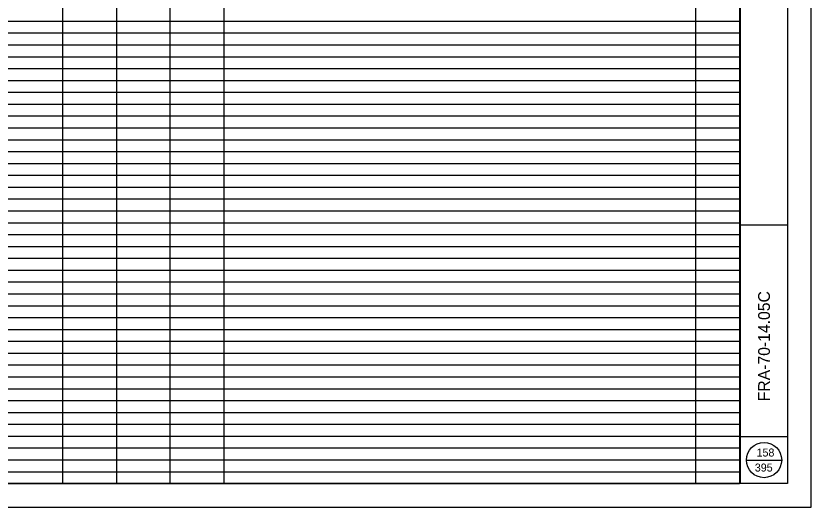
# Model space of a CAD drawing. Extents: x 1826847 to 2221677, y 500657 to 714743.
# Drawn here: x 1827702 to 1828547, y 713643 to 714165 of the extents above; entities that cross this region are included whole.
import ezdxf

# ---------------------------------------------------------------- set-up
doc = ezdxf.new("R2010")
doc.units = 0
for name, color, linetype in [('SH_Border', 7, 'Continuous'), ('SH_Cut_Line', 7, 'Continuous'), ('SH_Data', 7, 'Continuous')]:
    doc.layers.add(name, color=color, linetype=linetype)

msp = doc.modelspace()

# ---------------------------------------------------------------- linework, layer by layer
at = {"layer": 'SH_Border'}
for p, q in [((1828471.62, 713668.08), (1828471.62, 714718.08)), ((1828471.62, 713943.08), (1828521.62, 713943.08)), ((1828471.62, 713718.08), (1828521.62, 713718.08))]:
    msp.add_line(p, q, dxfattribs=at)
msp.add_lwpolyline([(1826946.62, 714718.08), (1828521.62, 714718.08), (1828521.62, 713668.08), (1826946.62, 713668.08)], close=True, dxfattribs=at)
at = {"layer": 'SH_Cut_Line'}
msp.add_lwpolyline([(1826846.62, 713643.08), (1828546.62, 713643.08), (1828546.62, 714743.08), (1826846.62, 714743.08)], close=True, dxfattribs=at)
at = {"layer": 'SH_Data'}
for p, q in [((1827751.22, 714222.48), (1827751.22, 714159.48)), ((1827808.82, 714222.48), (1827808.82, 714159.48)), ((1827865.22, 714222.48), (1827865.22, 714159.48)), ((1827922.82, 714222.48), (1827922.82, 714159.48)), ((1828423.82, 714222.48), (1828423.82, 714159.48)), ((1828470.62, 714222.48), (1828470.62, 714159.48)), ((1827648.62, 714159.48), (1827808.82, 714159.48)), ((1827751.22, 714159.48), (1827751.22, 714096.48)), ((1827808.82, 714159.48), (1827865.22, 714159.48)), ((1827808.82, 714159.48), (1827808.82, 714096.48)), ((1827865.22, 714159.48), (1827922.82, 714159.48)), ((1827865.22, 714159.48), (1827865.22, 714096.48)), ((1827922.82, 714159.48), (1828470.62, 714159.48)), ((1827922.82, 714159.48), (1827922.82, 714096.48)), ((1828423.82, 714159.48), (1828423.82, 714096.48)), ((1828470.62, 714159.48), (1828470.62, 714096.48)), ((1827648.62, 714146.88), (1827808.82, 714146.88)), ((1827808.82, 714146.88), (1827865.22, 714146.88)), ((1827865.22, 714146.88), (1827922.82, 714146.88)), ((1827922.82, 714146.88), (1828470.62, 714146.88)), ((1827648.62, 714134.28), (1827808.82, 714134.28)), ((1827808.82, 714134.28), (1827865.22, 714134.28)), ((1827865.22, 714134.28), (1827922.82, 714134.28)), ((1827922.82, 714134.28), (1828470.62, 714134.28)), ((1827648.62, 714121.68), (1827808.82, 714121.68)), ((1827808.82, 714121.68), (1827865.22, 714121.68)), ((1827865.22, 714121.68), (1827922.82, 714121.68)), ((1827922.82, 714121.68), (1828470.62, 714121.68)), ((1827648.62, 714109.08), (1827808.82, 714109.08)), ((1827808.82, 714109.08), (1827865.22, 714109.08)), ((1827865.22, 714109.08), (1827922.82, 714109.08)), ((1827922.82, 714109.08), (1828470.62, 714109.08)), ((1827648.62, 714096.48), (1827808.82, 714096.48)), ((1827751.22, 714096.48), (1827751.22, 714033.48)), ((1827808.82, 714096.48), (1827865.22, 714096.48)), ((1827808.82, 714096.48), (1827808.82, 714033.48)), ((1827865.22, 714096.48), (1827922.82, 714096.48)), ((1827865.22, 714096.48), (1827865.22, 714033.48)), ((1827922.82, 714096.48), (1828470.62, 714096.48)), ((1827922.82, 714096.48), (1827922.82, 714033.48)), ((1828423.82, 714096.48), (1828423.82, 714033.48)), ((1828470.62, 714096.48), (1828470.62, 714033.48)), ((1827648.62, 714083.88), (1827808.82, 714083.88)), ((1827808.82, 714083.88), (1827865.22, 714083.88)), ((1827865.22, 714083.88), (1827922.82, 714083.88)), ((1827922.82, 714083.88), (1828470.62, 714083.88)), ((1827648.62, 714071.28), (1827808.82, 714071.28)), ((1827808.82, 714071.28), (1827865.22, 714071.28)), ((1827865.22, 714071.28), (1827922.82, 714071.28)), ((1827922.82, 714071.28), (1828470.62, 714071.28)), ((1827648.62, 714058.68), (1827808.82, 714058.68)), ((1827808.82, 714058.68), (1827865.22, 714058.68)), ((1827865.22, 714058.68), (1827922.82, 714058.68)), ((1827922.82, 714058.68), (1828470.62, 714058.68)), ((1827648.62, 714046.08), (1827808.82, 714046.08)), ((1827808.82, 714046.08), (1827865.22, 714046.08)), ((1827865.22, 714046.08), (1827922.82, 714046.08)), ((1827922.82, 714046.08), (1828470.62, 714046.08)), ((1827648.62, 714033.48), (1827808.82, 714033.48)), ((1827751.22, 714033.48), (1827751.22, 713970.48)), ((1827808.82, 714033.48), (1827865.22, 714033.48)), ((1827808.82, 714033.48), (1827808.82, 713970.48)), ((1827865.22, 714033.48), (1827922.82, 714033.48)), ((1827865.22, 714033.48), (1827865.22, 713970.48)), ((1827922.82, 714033.48), (1828470.62, 714033.48)), ((1827922.82, 714033.48), (1827922.82, 713970.48)), ((1828423.82, 714033.48), (1828423.82, 713970.48)), ((1828470.62, 714033.48), (1828470.62, 713970.48)), ((1827648.62, 714020.88), (1827808.82, 714020.88)), ((1827808.82, 714020.88), (1827865.22, 714020.88)), ((1827865.22, 714020.88), (1827922.82, 714020.88)), ((1827922.82, 714020.88), (1828470.62, 714020.88)), ((1827648.62, 714008.28), (1827808.82, 714008.28)), ((1827808.82, 714008.28), (1827865.22, 714008.28)), ((1827865.22, 714008.28), (1827922.82, 714008.28)), ((1827922.82, 714008.28), (1828470.62, 714008.28)), ((1827648.62, 713995.68), (1827808.82, 713995.68)), ((1827808.82, 713995.68), (1827865.22, 713995.68)), ((1827865.22, 713995.68), (1827922.82, 713995.68)), ((1827922.82, 713995.68), (1828470.62, 713995.68)), ((1827648.62, 713983.08), (1827808.82, 713983.08)), ((1827808.82, 713983.08), (1827865.22, 713983.08)), ((1827865.22, 713983.08), (1827922.82, 713983.08)), ((1827922.82, 713983.08), (1828470.62, 713983.08)), ((1827648.62, 713970.48), (1827808.82, 713970.48)), ((1827751.22, 713970.48), (1827751.22, 713907.48)), ((1827808.82, 713970.48), (1827865.22, 713970.48)), ((1827808.82, 713970.48), (1827808.82, 713907.48)), ((1827865.22, 713970.48), (1827922.82, 713970.48)), ((1827865.22, 713970.48), (1827865.22, 713907.48)), ((1827922.82, 713970.48), (1828470.62, 713970.48)), ((1827922.82, 713970.48), (1827922.82, 713907.48)), ((1828423.82, 713970.48), (1828423.82, 713907.48)), ((1828470.62, 713970.48), (1828470.62, 713907.48)), ((1827648.62, 713957.88), (1827808.82, 713957.88)), ((1827808.82, 713957.88), (1827865.22, 713957.88)), ((1827865.22, 713957.88), (1827922.82, 713957.88)), ((1827922.82, 713957.88), (1828470.62, 713957.88)), ((1827648.62, 713945.28), (1827808.82, 713945.28)), ((1827808.82, 713945.28), (1827865.22, 713945.28)), ((1827865.22, 713945.28), (1827922.82, 713945.28)), ((1827922.82, 713945.28), (1828470.62, 713945.28)), ((1827648.62, 713932.68), (1827808.82, 713932.68)), ((1827808.82, 713932.68), (1827865.22, 713932.68)), ((1827865.22, 713932.68), (1827922.82, 713932.68)), ((1827922.82, 713932.68), (1828470.62, 713932.68)), ((1827648.62, 713920.08), (1827808.82, 713920.08)), ((1827808.82, 713920.08), (1827865.22, 713920.08)), ((1827865.22, 713920.08), (1827922.82, 713920.08)), ((1827922.82, 713920.08), (1828470.62, 713920.08)), ((1827648.62, 713907.48), (1827808.82, 713907.48)), ((1827751.22, 713907.48), (1827751.22, 713844.48)), ((1827808.82, 713907.48), (1827865.22, 713907.48)), ((1827808.82, 713907.48), (1827808.82, 713844.48)), ((1827865.22, 713907.48), (1827922.82, 713907.48)), ((1827865.22, 713907.48), (1827865.22, 713844.48)), ((1827922.82, 713907.48), (1828470.62, 713907.48)), ((1827922.82, 713907.48), (1827922.82, 713844.48)), ((1828423.82, 713907.48), (1828423.82, 713844.48)), ((1828470.62, 713907.48), (1828470.62, 713844.48)), ((1827648.62, 713894.88), (1827808.82, 713894.88)), ((1827808.82, 713894.88), (1827865.22, 713894.88)), ((1827865.22, 713894.88), (1827922.82, 713894.88)), ((1827922.82, 713894.88), (1828470.62, 713894.88)), ((1827648.62, 713882.28), (1827808.82, 713882.28)), ((1827808.82, 713882.28), (1827865.22, 713882.28)), ((1827865.22, 713882.28), (1827922.82, 713882.28)), ((1827922.82, 713882.28), (1828470.62, 713882.28)), ((1827648.62, 713869.68), (1827808.82, 713869.68)), ((1827808.82, 713869.68), (1827865.22, 713869.68)), ((1827865.22, 713869.68), (1827922.82, 713869.68)), ((1827922.82, 713869.68), (1828470.62, 713869.68)), ((1827648.62, 713857.08), (1827808.82, 713857.08)), ((1827808.82, 713857.08), (1827865.22, 713857.08)), ((1827865.22, 713857.08), (1827922.82, 713857.08)), ((1827922.82, 713857.08), (1828470.62, 713857.08)), ((1827648.62, 713844.48), (1827808.82, 713844.48)), ((1827751.22, 713844.48), (1827751.22, 713781.48)), ((1827808.82, 713844.48), (1827865.22, 713844.48)), ((1827808.82, 713844.48), (1827808.82, 713781.48)), ((1827865.22, 713844.48), (1827922.82, 713844.48)), ((1827865.22, 713844.48), (1827865.22, 713781.48)), ((1827922.82, 713844.48), (1828470.62, 713844.48)), ((1827922.82, 713844.48), (1827922.82, 713781.48)), ((1828423.82, 713844.48), (1828423.82, 713781.48)), ((1828470.62, 713844.48), (1828470.62, 713781.48)), ((1827648.62, 713831.88), (1827808.82, 713831.88)), ((1827808.82, 713831.88), (1827865.22, 713831.88)), ((1827865.22, 713831.88), (1827922.82, 713831.88)), ((1827922.82, 713831.88), (1828470.62, 713831.88)), ((1827648.62, 713819.28), (1827808.82, 713819.28)), ((1827808.82, 713819.28), (1827865.22, 713819.28)), ((1827865.22, 713819.28), (1827922.82, 713819.28)), ((1827922.82, 713819.28), (1828470.62, 713819.28)), ((1827648.62, 713806.68), (1827808.82, 713806.68)), ((1827808.82, 713806.68), (1827865.22, 713806.68)), ((1827865.22, 713806.68), (1827922.82, 713806.68)), ((1827922.82, 713806.68), (1828470.62, 713806.68)), ((1827648.62, 713794.08), (1827808.82, 713794.08)), ((1827808.82, 713794.08), (1827865.22, 713794.08)), ((1827865.22, 713794.08), (1827922.82, 713794.08)), ((1827922.82, 713794.08), (1828470.62, 713794.08)), ((1827648.62, 713781.48), (1827808.82, 713781.48)), ((1827751.22, 713781.48), (1827751.22, 713768.88)), ((1827808.82, 713781.48), (1827865.22, 713781.48)), ((1827808.82, 713781.48), (1827808.82, 713768.88)), ((1827865.22, 713781.48), (1827922.82, 713781.48)), ((1827865.22, 713781.48), (1827865.22, 713768.88)), ((1827922.82, 713781.48), (1828470.62, 713781.48)), ((1827922.82, 713781.48), (1827922.82, 713768.88)), ((1828423.82, 713781.48), (1828423.82, 713768.88)), ((1828470.62, 713781.48), (1828470.62, 713768.88)), ((1827648.62, 713768.88), (1827808.82, 713768.88)), ((1827751.22, 713768.88), (1827751.22, 713756.28)), ((1827808.82, 713768.88), (1827865.22, 713768.88)), ((1827808.82, 713768.88), (1827808.82, 713756.28)), ((1827865.22, 713768.88), (1827922.82, 713768.88)), ((1827865.22, 713768.88), (1827865.22, 713756.28)), ((1827922.82, 713768.88), (1828470.62, 713768.88)), ((1827922.82, 713768.88), (1827922.82, 713756.28)), ((1828423.82, 713768.88), (1828423.82, 713756.28)), ((1828470.62, 713768.88), (1828470.62, 713756.28)), ((1827648.62, 713756.28), (1827808.82, 713756.28)), ((1827751.22, 713756.28), (1827751.22, 713743.68)), ((1827808.82, 713756.28), (1827865.22, 713756.28)), ((1827808.82, 713756.28), (1827808.82, 713743.68)), ((1827865.22, 713756.28), (1827922.82, 713756.28)), ((1827865.22, 713756.28), (1827865.22, 713743.68)), ((1827922.82, 713756.28), (1828470.62, 713756.28)), ((1827922.82, 713756.28), (1827922.82, 713743.68)), ((1828423.82, 713756.28), (1828423.82, 713743.68)), ((1828470.62, 713756.28), (1828470.62, 713743.68)), ((1827648.62, 713743.68), (1827808.82, 713743.68)), ((1827751.22, 713743.68), (1827751.22, 713731.08)), ((1827808.82, 713743.68), (1827865.22, 713743.68)), ((1827808.82, 713743.68), (1827808.82, 713731.08)), ((1827865.22, 713743.68), (1827922.82, 713743.68)), ((1827865.22, 713743.68), (1827865.22, 713731.08)), ((1827922.82, 713743.68), (1828470.62, 713743.68)), ((1827922.82, 713743.68), (1827922.82, 713731.08)), ((1828423.82, 713743.68), (1828423.82, 713731.08)), ((1828470.62, 713743.68), (1828470.62, 713731.08)), ((1827648.62, 713731.08), (1827808.82, 713731.08)), ((1827751.22, 713731.08), (1827751.22, 713718.48)), ((1827808.82, 713731.08), (1827865.22, 713731.08)), ((1827808.82, 713731.08), (1827808.82, 713718.48)), ((1827865.22, 713731.08), (1827922.82, 713731.08)), ((1827865.22, 713731.08), (1827865.22, 713718.48)), ((1827922.82, 713731.08), (1828470.62, 713731.08)), ((1827922.82, 713731.08), (1827922.82, 713718.48)), ((1828423.82, 713731.08), (1828423.82, 713718.48)), ((1828470.62, 713731.08), (1828470.62, 713718.48)), ((1827648.62, 713718.48), (1827808.82, 713718.48)), ((1827751.22, 713718.48), (1827751.22, 713705.88)), ((1827808.82, 713718.48), (1827865.22, 713718.48)), ((1827808.82, 713718.48), (1827808.82, 713705.88)), ((1827865.22, 713718.48), (1827922.82, 713718.48)), ((1827865.22, 713718.48), (1827865.22, 713705.88)), ((1827922.82, 713718.48), (1828470.62, 713718.48)), ((1827922.82, 713718.48), (1827922.82, 713705.88)), ((1828423.82, 713718.48), (1828423.82, 713705.88)), ((1828470.62, 713718.48), (1828470.62, 713705.88)), ((1827648.62, 713705.88), (1827808.82, 713705.88)), ((1827751.22, 713705.88), (1827751.22, 713668.08)), ((1827808.82, 713705.88), (1827865.22, 713705.88)), ((1827808.82, 713705.88), (1827808.82, 713668.08)), ((1827865.22, 713705.88), (1827922.82, 713705.88)), ((1827865.22, 713705.88), (1827865.22, 713668.08)), ((1827922.82, 713705.88), (1828470.62, 713705.88)), ((1827922.82, 713705.88), (1827922.82, 713668.08)), ((1828423.82, 713705.88), (1828423.82, 713668.08)), ((1828470.62, 713705.88), (1828470.62, 713668.08)), ((1827648.62, 713693.28), (1827808.82, 713693.28)), ((1827808.82, 713693.28), (1827865.22, 713693.28)), ((1827865.22, 713693.28), (1827922.82, 713693.28)), ((1827922.82, 713693.28), (1828470.62, 713693.28)), ((1828477.87, 713693.08), (1828515.37, 713693.08)), ((1827648.62, 713680.68), (1827808.82, 713680.68)), ((1827808.82, 713680.68), (1827865.22, 713680.68)), ((1827865.22, 713680.68), (1827922.82, 713680.68)), ((1827922.82, 713680.68), (1828470.62, 713680.68)), ((1827648.62, 713668.08), (1827808.82, 713668.08)), ((1827808.82, 713668.08), (1827865.22, 713668.08)), ((1827865.22, 713668.08), (1827922.82, 713668.08)), ((1827922.82, 713668.08), (1828470.62, 713668.08))]:
    msp.add_line(p, q, dxfattribs=at)
msp.add_circle((1828496.62, 713693.08), 18.75, dxfattribs=at)

# ---------------------------------------------------------------- texts
msp.add_text('FRA-70-14.05C', height=12.5, rotation=90, dxfattribs=at).set_placement((1828502.87, 713755.54))
for s, p in [('158', (1828488.65, 713696.83)), ('395', (1828486.81, 713680.83))]:
    msp.add_text(s, height=8.5, dxfattribs=at).set_placement(p)

doc.saveas('drawing.dxf')
